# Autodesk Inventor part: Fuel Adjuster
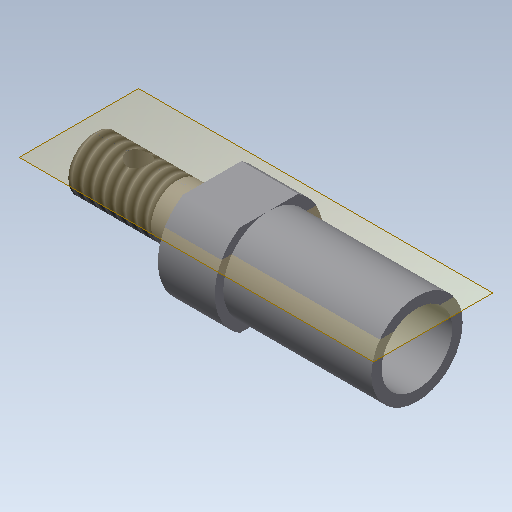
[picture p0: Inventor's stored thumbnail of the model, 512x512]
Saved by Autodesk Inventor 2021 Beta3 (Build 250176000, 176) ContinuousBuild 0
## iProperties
Created: 2012-08
Part Number: Fuel Adjuster
Material: Generic
Document SubType Name: Modeling
Designer: John
Density: 1 g/cm^3
Appearance: Default
Author: John
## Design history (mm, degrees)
sketch "Sketch1"
  geometry: C1 r 1.969 at (0, 0); 1 further point
  constraints: 1 centre point, 1 coincident
  dimensions: "d0" = 3.937 diameter of C1
extrude "Extrusion1" new body sketch "Sketch1" distance "d1" = 8.636; taper "d2" = 0 deg
sketch "Sketch2"
  geometry: C1 r 1.969 at (0, 0) reference; C2 r 4.001 at (0, 0)
  constraints: 1 centre point, 1 coincident
  dimensions: "d3" = 8.001 diameter of C2
extrude "Extrusion2" join sketch "Sketch2" distance "d4" = 4.191; taper "d5" = 0 deg
sketch "Sketch3"
  geometry: C1 r 4.001 at (0, 0) reference; C2 r 3.365 at (0, 0)
  constraints: 1 centre point, 1 coincident
  dimensions: "d6" = 6.731 diameter of C2
extrude "Extrusion3" join sketch "Sketch3" distance "d7" = 10.922; taper "d8" = 0 deg
sketch "Sketch4"
  geometry: L1 (-3.365, 2.163)-(-3.365, -2.163); L2 (3.365, 2.163)-(3.365, -2.163); C1 r 3.365 at (0, 0) reference; A1 r 4.001 centre (0, 0) between (-3.365, 2.163) and (-3.365, -2.163) reference
  constraints: 4 end point, 4 point on circle, 2 tangent, 1 parallel, 1 vertical
extrude "Extrusion4" cut sketch "Sketch4" extent not by distance; stored distance "d9" = 10.922; taper "d10" = 0 deg
sketch "Sketch5"
  geometry: C1 r 3.365 at (0, 0) reference
hole "Hole1" sketch "Sketch5" at (0, 0) diameter "d11" = 5.207; stored, may be unused: countersink angle "d15" = 82 deg, drill point angle "d17" = 0 deg; dims "d12" = 19.05, "d13" = 9.525, "d14" = 6.35, "d16" = 5.08
sketch "Sketch6"
  geometry: C1 r 2.603 at (0, 0) reference
hole "Hole2" sketch "Sketch6" at (0, 0) diameter "d18" = 3.937; stored, may be unused: countersink angle "d22" = 82 deg, drill point angle "d24" = 0 deg; dims "d19" = 19.05, "d20" = 9.525, "d21" = 6.35, "d23" = 4.953
sketch "Sketch7"
  geometry: C1 r 1.968 at (0, 0) reference
hole "Hole3" sketch "Sketch7" at (0, 0) diameter "d25" = 1.5748; stored, may be unused: countersink angle "d29" = 82 deg, drill point angle "d31" = 0 deg; dims "d26" = 19.05, "d27" = 9.525, "d28" = 6.35, "d30" = 4.953
workplane "Work Plane1"
sketch "Sketch8"
  geometry: L1 (0, 0)-(3.212, 0)
  constraints: 2 end point, 1 horizontal
hole "Hole4" sketch "Sketch8" at (3.212, 0) diameter "d32" = 1.651; stored, may be unused: countersink angle "d36" = 82 deg, drill point angle "d38" = 118 deg; dims "d33" = 19.05, "d34" = 9.525, "d35" = 6.35, "d37" = 1.5875
thread "Thread1" dims "d39" = 25.4, "d40" = 0
thread "Thread2" dims "d41" = 7.62, "d42" = 2.54
body "Solid1"
